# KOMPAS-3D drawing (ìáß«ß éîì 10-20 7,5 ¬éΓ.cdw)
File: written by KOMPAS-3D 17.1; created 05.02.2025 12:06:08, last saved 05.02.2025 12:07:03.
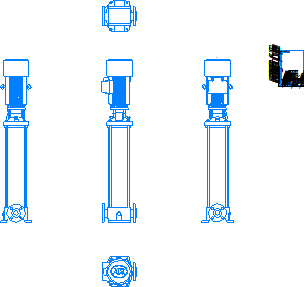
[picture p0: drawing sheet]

Sheet 1: A4, portrait

Title block, sheet 1: name: Насос ВМН 10-20 / 7,5 кВт; designation: Насос ВМН 10-20 7,5 кВт; material: Сталь 10  ГОСТ 1050-2013; mass: 266,58; sheets: 1; sheet format: A4; stored path: \\adlc.lan\data\АДЛ_ПКД\3D-модели\ADL production\Насосы ГРАНПАМП\Насосы ВМН\ВМН10\KOMPAS 3D\Насос ВМН 10-20 7,5 кВт.cdw

Views: Проекционный вид 2, Проекционный вид 3, Проекционный вид 4, Проекционный вид 5
Referenced files in \\adlc.lan\data\АДЛ_ПКД\3D-модели\ADL production\Насосы ГРАНПАМП\Насосы ВМН\ВМН10\KOMPAS 3D\: Насос ВМН 10-20 7,5 кВт.m3d
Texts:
  Andrey
  АДЛ
Dimensions and other numbers on the sheet: 1:1; 1; 7,5 кВт; 266,58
